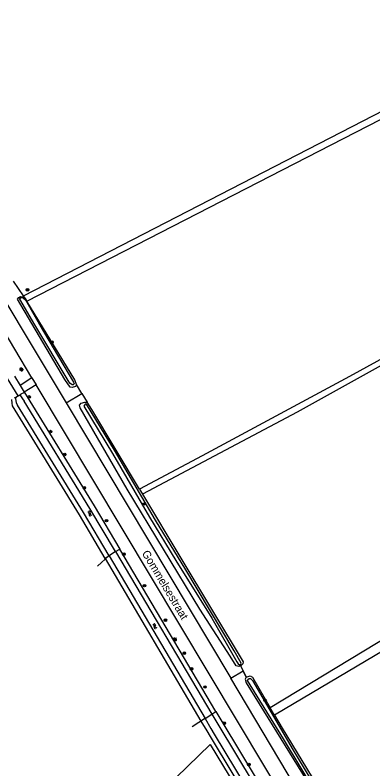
# Model space of a CAD drawing. Extents: x 137000 to 140001, y 403500 to 406000.
# Drawn here: x 139203.4 to 139315.1, y 404363 to 404598.3 of the extents above; entities that cross this region are included whole.
import ezdxf

# ---------------------------------------------------------------- set-up
doc = ezdxf.new("R2010")
doc.units = 0
for name, color, linetype in [('gg-afsc-draadraster', 7, 'Continuous'), ('gg-afsc-hekwerk', 7, 'Continuous'), ('gg-afsc-lijn draadraster', 7, 'Continuous'), ('gg-anno-openbare ruimte label', 7, 'Continuous'), ('gg-knt-bronhoudergrens', 7, 'Continuous'), ('gg-knt-verharding', 7, 'Continuous'), ('gg-kntw-bovenkant insteek waterloop', 7, 'Continuous'), ('gg-kntw-waterlijn', 7, 'Continuous'), ('gg-kwrk-duiker nz buis', 7, 'Continuous'), ('gt-grn-groengrens', 7, 'Continuous'), ('gt-grn-groengrens NZ', 7, 'Continuous'), ('gt-grn-vlakafsluiter', 7, 'Continuous'), ('gt-grn-weggrens', 7, 'Continuous'), ('gt-symb-boom', 7, 'Continuous'), ('gt-symb-lichtmast', 7, 'Continuous'), ('gt-symb-watersymbool', 7, 'Continuous')]:
    doc.layers.add(name, color=color, linetype=linetype)

# ---------------------------------------------------------------- blocks, each defined once
blk = doc.blocks.new('gt0-BOOM')
at = {"layer": 'gt-symb-boom'}
for radius in [0.4, 0.2]:
    blk.add_circle((0, 0), radius, dxfattribs=at)
blk = doc.blocks.new('gt0-WA')
at = {"layer": 'gt-symb-watersymbool'}
for centre, start, end in [((-0.32, 0.02), 28.0725, 151.9275), ((0.43, 0.42), 208.0725, 331.9275), ((-0.32, -0.43), 28.0725, 151.9275), ((0.43, -0.03), 208.0725, 331.9275)]:
    blk.add_arc(centre, 0.425, start, end, dxfattribs=at)
blk = doc.blocks.new('gt0-LMAST')
at = {"layer": 'gt-symb-lichtmast'}
for p, q in [((-0.18, 0.17), (-0.45, 0.44)), ((-0.01, 0.25), (-0.01, 0.62)), ((0.17, 0.17), (0.44, 0.44)), ((-0.26, 0), (-0.63, 0)), ((-0.18, -0.18), (-0.45, -0.45)), ((-0.01, -0.25), (-0.01, -0.63)), ((0.44, -0.45), (0.17, -0.18)), ((0.24, 0), (0.62, 0))]:
    blk.add_line(p, q, dxfattribs=at)
blk.add_circle((-0.01, 0), 0.25, dxfattribs=at)

msp = doc.modelspace()

# ---------------------------------------------------------------- linework, layer by layer
at = {"layer": 'gg-afsc-draadraster'}
msp.add_lwpolyline([(139158.03, 404195.16), (139156.15, 404194.19), (139125.6, 404238.27), (139160.28, 404272.51), (139201.92, 404311.78), (139225.48, 404332.97), (139264.34, 404370.64)], dxfattribs=at)
at = {"layer": 'gg-afsc-hekwerk'}
for p, q in [((139273.76, 404395.2), (139274.59, 404393.56)), ((139274.59, 404393.56), (139275.58, 404391.62))]:
    msp.add_line(p, q, dxfattribs=at)
at = {"layer": 'gg-afsc-lijn draadraster'}
msp.add_lwpolyline([(139158.03, 404195.16), (139156.15, 404194.19), (139125.6, 404238.27), (139160.28, 404272.51), (139201.92, 404311.78), (139225.48, 404332.97), (139264.34, 404370.64)], dxfattribs=at)
at = {"layer": 'gg-knt-bronhoudergrens'}
for p, q in [((139206.08, 404510.72), (139202.91, 404515.31)), ((139224.28, 404480.19), (139222.57, 404482.98)), ((139224.28, 404480.19), (139225.97, 404477.44)), ((139264.34, 404370.64), (139311.83, 404292.17))]:
    msp.add_line(p, q, dxfattribs=at)
msp.add_lwpolyline([(139548.39, 404472.83), (139549.75, 404473.82), (139521.37, 404518.71), (139452.72, 404479.52), (139284.39, 404379.8)], dxfattribs=at)
at = {"layer": 'gg-knt-verharding'}
for p, q in [((139208.68, 404485.07), (139139.1, 404601.02)), ((139208.68, 404485.07), (139209.99, 404482.89)), ((139219.39, 404477.27), (139270.76, 404391.27)), ((139309.55, 404326.33), (139270.76, 404391.27))]:
    msp.add_line(p, q, dxfattribs=at)
for points in [[(139152.21, 404589.23), (139214.74, 404485.05), (139219.39, 404477.27)], [(139337.94, 404269.03), (139308.54, 404318.27), (139209.99, 404482.89)]]:
    msp.add_lwpolyline(points, dxfattribs=at)
at = {"layer": 'gg-kntw-bovenkant insteek waterloop'}
for p, q in [((139206.65, 404509.9), (139207.16, 404509.06)), ((139203.29, 404478.83), (139203.63, 404479.03)), ((139203.63, 404479.03), (139204.97, 404479.79)), ((139204.97, 404479.79), (139205.26, 404479.96)), ((139206.42, 404480.46), (139205.26, 404479.96)), ((139266.12, 404380.94), (139236.09, 404431.63)), ((139231.53, 404428.67), (139261.46, 404377.91)), ((139284.39, 404379.8), (139283.07, 404382.08))]:
    msp.add_line(p, q, dxfattribs=at)
for points in [[(139486.97, 404585.18), (139433.78, 404555.48), (139393.43, 404533.53), (139354.63, 404511.23), (139307.8, 404485.51), (139261.86, 404460.7), (139242.27, 404450.3)], [(139373.49, 404519.84), (139362.42, 404513.83), (139291.52, 404474.35), (139243.21, 404448.73)], [(139222.57, 404482.98), (139222.29, 404482.33), (139221.29, 404482.08), (139220.67, 404482.2), (139218.97, 404484.59), (139204.23, 404509.59), (139204.64, 404510.11), (139205.11, 404510.43), (139205.77, 404510.35), (139206.65, 404509.9)], [(139222.57, 404482.98), (139222.14, 404484.44), (139207.16, 404509.06)], [(139206.42, 404480.46), (139228.11, 404445.09), (139236.09, 404431.63)], [(139231.53, 404428.67), (139223.51, 404442.27), (139202.64, 404476.29), (139202.52, 404477.12), (139202.48, 404478.29)], [(139273.76, 404395.2), (139273.28, 404394.98), (139272.43, 404395.2), (139270.58, 404398.15), (139261.05, 404412.82), (139238.45, 404450.28), (139223.71, 404475.68), (139223.5, 404476.51), (139224.11, 404477.16), (139225.18, 404477.53), (139225.97, 404477.44)], [(139242.27, 404450.3), (139227.44, 404475.23), (139225.97, 404477.44)], [(139243.21, 404448.73), (139255.12, 404428.73), (139274.57, 404396.4), (139274.53, 404395.84), (139273.95, 404395.29), (139273.76, 404395.2)], [(139275.58, 404391.62), (139275.2, 404391), (139275.57, 404389.87), (139297.15, 404354.91), (139311.15, 404330.95), (139311.81, 404330.93), (139312.62, 404331.71), (139312.9, 404332.3)], [(139275.58, 404391.62), (139276.85, 404392.05), (139277.53, 404391.67), (139283.07, 404382.08)], [(139266.12, 404380.94), (139268.01, 404377.76), (139317.92, 404294.83)], [(139284.39, 404379.8), (139286.77, 404375.69), (139303.79, 404347.82), (139312.9, 404332.3)], [(139261.46, 404377.91), (139263.24, 404374.88), (139264.32, 404373.09), (139312.62, 404292.85), (139313.25, 404291.79)]]:
    msp.add_lwpolyline(points, dxfattribs=at)
at = {"layer": 'gg-kntw-waterlijn'}
for p, q in [((139242.27, 404450.3), (139243.21, 404448.73)), ((139232.79, 404429.49), (139262.72, 404378.73)), ((139234.83, 404430.81), (139264.87, 404380.12))]:
    msp.add_line(p, q, dxfattribs=at)
for points in [[(139204.97, 404509.63), (139205.04, 404509.96), (139205.29, 404510.07), (139205.66, 404510.16), (139206.1, 404510), (139206.66, 404509.41), (139212.3, 404499.54), (139221.7, 404483.69), (139221.9, 404483.17), (139221.61, 404482.9), (139221.22, 404482.94), (139220.57, 404483.38), (139219.99, 404484.29), (139209.65, 404501.61), (139204.97, 404509.63)], [(139203.63, 404479.03), (139203.61, 404478.53), (139203.64, 404478), (139203.83, 404477.27), (139204.25, 404476.53)], [(139204.97, 404479.79), (139205.74, 404478.57), (139206.32, 404477.76)], [(139232.79, 404429.49), (139224.79, 404443.04), (139204.25, 404476.53)], [(139234.83, 404430.81), (139226.82, 404444.32), (139206.32, 404477.76)], [(139225.73, 404476.81), (139225.35, 404476.84), (139225.08, 404476.55), (139224.91, 404476.19), (139233.84, 404461.47), (139245.43, 404441.59), (139253.62, 404428.03), (139264.79, 404410.08), (139272.6, 404396.41), (139273.08, 404395.8), (139273.47, 404395.53), (139273.94, 404395.72), (139273.98, 404396.01), (139271.79, 404399.9), (139256.76, 404425.14), (139247.3, 404440.66), (139234.48, 404462.53), (139225.73, 404476.81)], [(139276.12, 404390.92), (139276.51, 404391.26), (139276.87, 404391.18), (139277.48, 404390.57), (139290.22, 404368.79), (139302.62, 404348.26), (139312.46, 404332.22), (139312.52, 404331.98), (139312.32, 404331.66), (139312, 404331.61), (139311.65, 404331.89), (139311.14, 404332.79), (139298.59, 404353.5), (139287.24, 404372.41), (139275.95, 404390.59), (139276.12, 404390.92)], [(139264.87, 404380.12), (139266.72, 404376.99), (139316.68, 404294.02)], [(139262.72, 404378.73), (139264.53, 404375.65), (139265.6, 404373.86), (139314.51, 404292.61)]]:
    msp.add_lwpolyline(points, dxfattribs=at)
at = {"layer": 'gg-kwrk-duiker nz buis'}
for p, q in [((139201.01, 404484.87), (139204.3, 404479.41)), ((139232.8, 404429.59), (139229.12, 404426.27)), ((139258.68, 404376.24), (139262.87, 404378.97))]:
    msp.add_line(p, q, dxfattribs=at)
at = {"layer": 'gt-grn-groengrens'}
msp.add_line((139399.74, 404452.73), (139283.07, 404382.08), dxfattribs=at)
for points in [[(139206.08, 404510.72), (139373.41, 404596.95), (139349.53, 404644.46), (139347.53, 404650.29), (139344.55, 404655.41), (139344.15, 404657.58), (139387.3, 404678.27)], [(139207.16, 404509.06), (139374.37, 404594.96), (139399.53, 404607.12), (139457.69, 404636.8)]]:
    msp.add_lwpolyline(points, dxfattribs=at)
at = {"layer": 'gt-grn-groengrens NZ'}
for p, q in [((139206.65, 404509.9), (139206.08, 404510.72)), ((139203.23, 404485.62), (139205.02, 404482.73)), ((139205.02, 404482.73), (139206.31, 404480.63)), ((139206.31, 404480.63), (139206.42, 404480.46)), ((139273.76, 404395.2), (139274.59, 404393.56)), ((139275.58, 404391.62), (139274.59, 404393.56))]:
    msp.add_line(p, q, dxfattribs=at)
at = {"layer": 'gt-grn-vlakafsluiter'}
for p, q in [((139234.83, 404430.81), (139236.09, 404431.63)), ((139232.79, 404429.49), (139231.53, 404428.67)), ((139234.83, 404430.81), (139232.79, 404429.49)), ((139262.72, 404378.73), (139264.87, 404380.12)), ((139264.87, 404380.12), (139266.12, 404380.94)), ((139262.72, 404378.73), (139261.46, 404377.91))]:
    msp.add_line(p, q, dxfattribs=at)
at = {"layer": 'gt-grn-weggrens'}
for p, q in [((139208.68, 404485.07), (139205.02, 404482.73)), ((139209.99, 404482.89), (139206.31, 404480.63)), ((139219.39, 404477.27), (139224.28, 404480.19)), ((139270.76, 404391.27), (139274.59, 404393.56))]:
    msp.add_line(p, q, dxfattribs=at)

# ---------------------------------------------------------------- block references
at = {"layer": 'gt-symb-boom'}
for p in [(139207.33, 404512.54), (139214.9, 404496.2), (139207.88, 404479.12), (139214.55, 404468.29), (139218.93, 404461.13), (139225.06, 404450.73), (139243.66, 404445.68), (139231.98, 404440.48), (139237.38, 404430.04), (139243.85, 404420.18), (139250.35, 404409.41), (139256.27, 404399.12), (139258.49, 404394.22), (139262.7, 404388.55), (139281.45, 404384.42), (139268.74, 404377.28), (139276.4, 404364.35)]:
    msp.add_blockref('gt0-BOOM', p, dxfattribs=at)
at = {"layer": 'gt-symb-lichtmast'}
for p in [(139205.41, 404487.67), (139253.33, 404403.43)]:
    msp.add_blockref('gt0-LMAST', p, dxfattribs=at)
at = {"layer": 'gt-symb-watersymbool', "rotation": 126.9958977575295}
for p in [(139226.76, 404442.67), (139247.07, 404407.49)]:
    msp.add_blockref('gt0-WA', p, dxfattribs=at)

# ---------------------------------------------------------------- texts
at = {"layer": 'gg-anno-openbare ruimte label'}
msp.add_text('Gommelsestraat', height=2.5, rotation=300.9, dxfattribs=at).set_placement((139242.91, 404430.33))

doc.saveas('drawing.dxf')
